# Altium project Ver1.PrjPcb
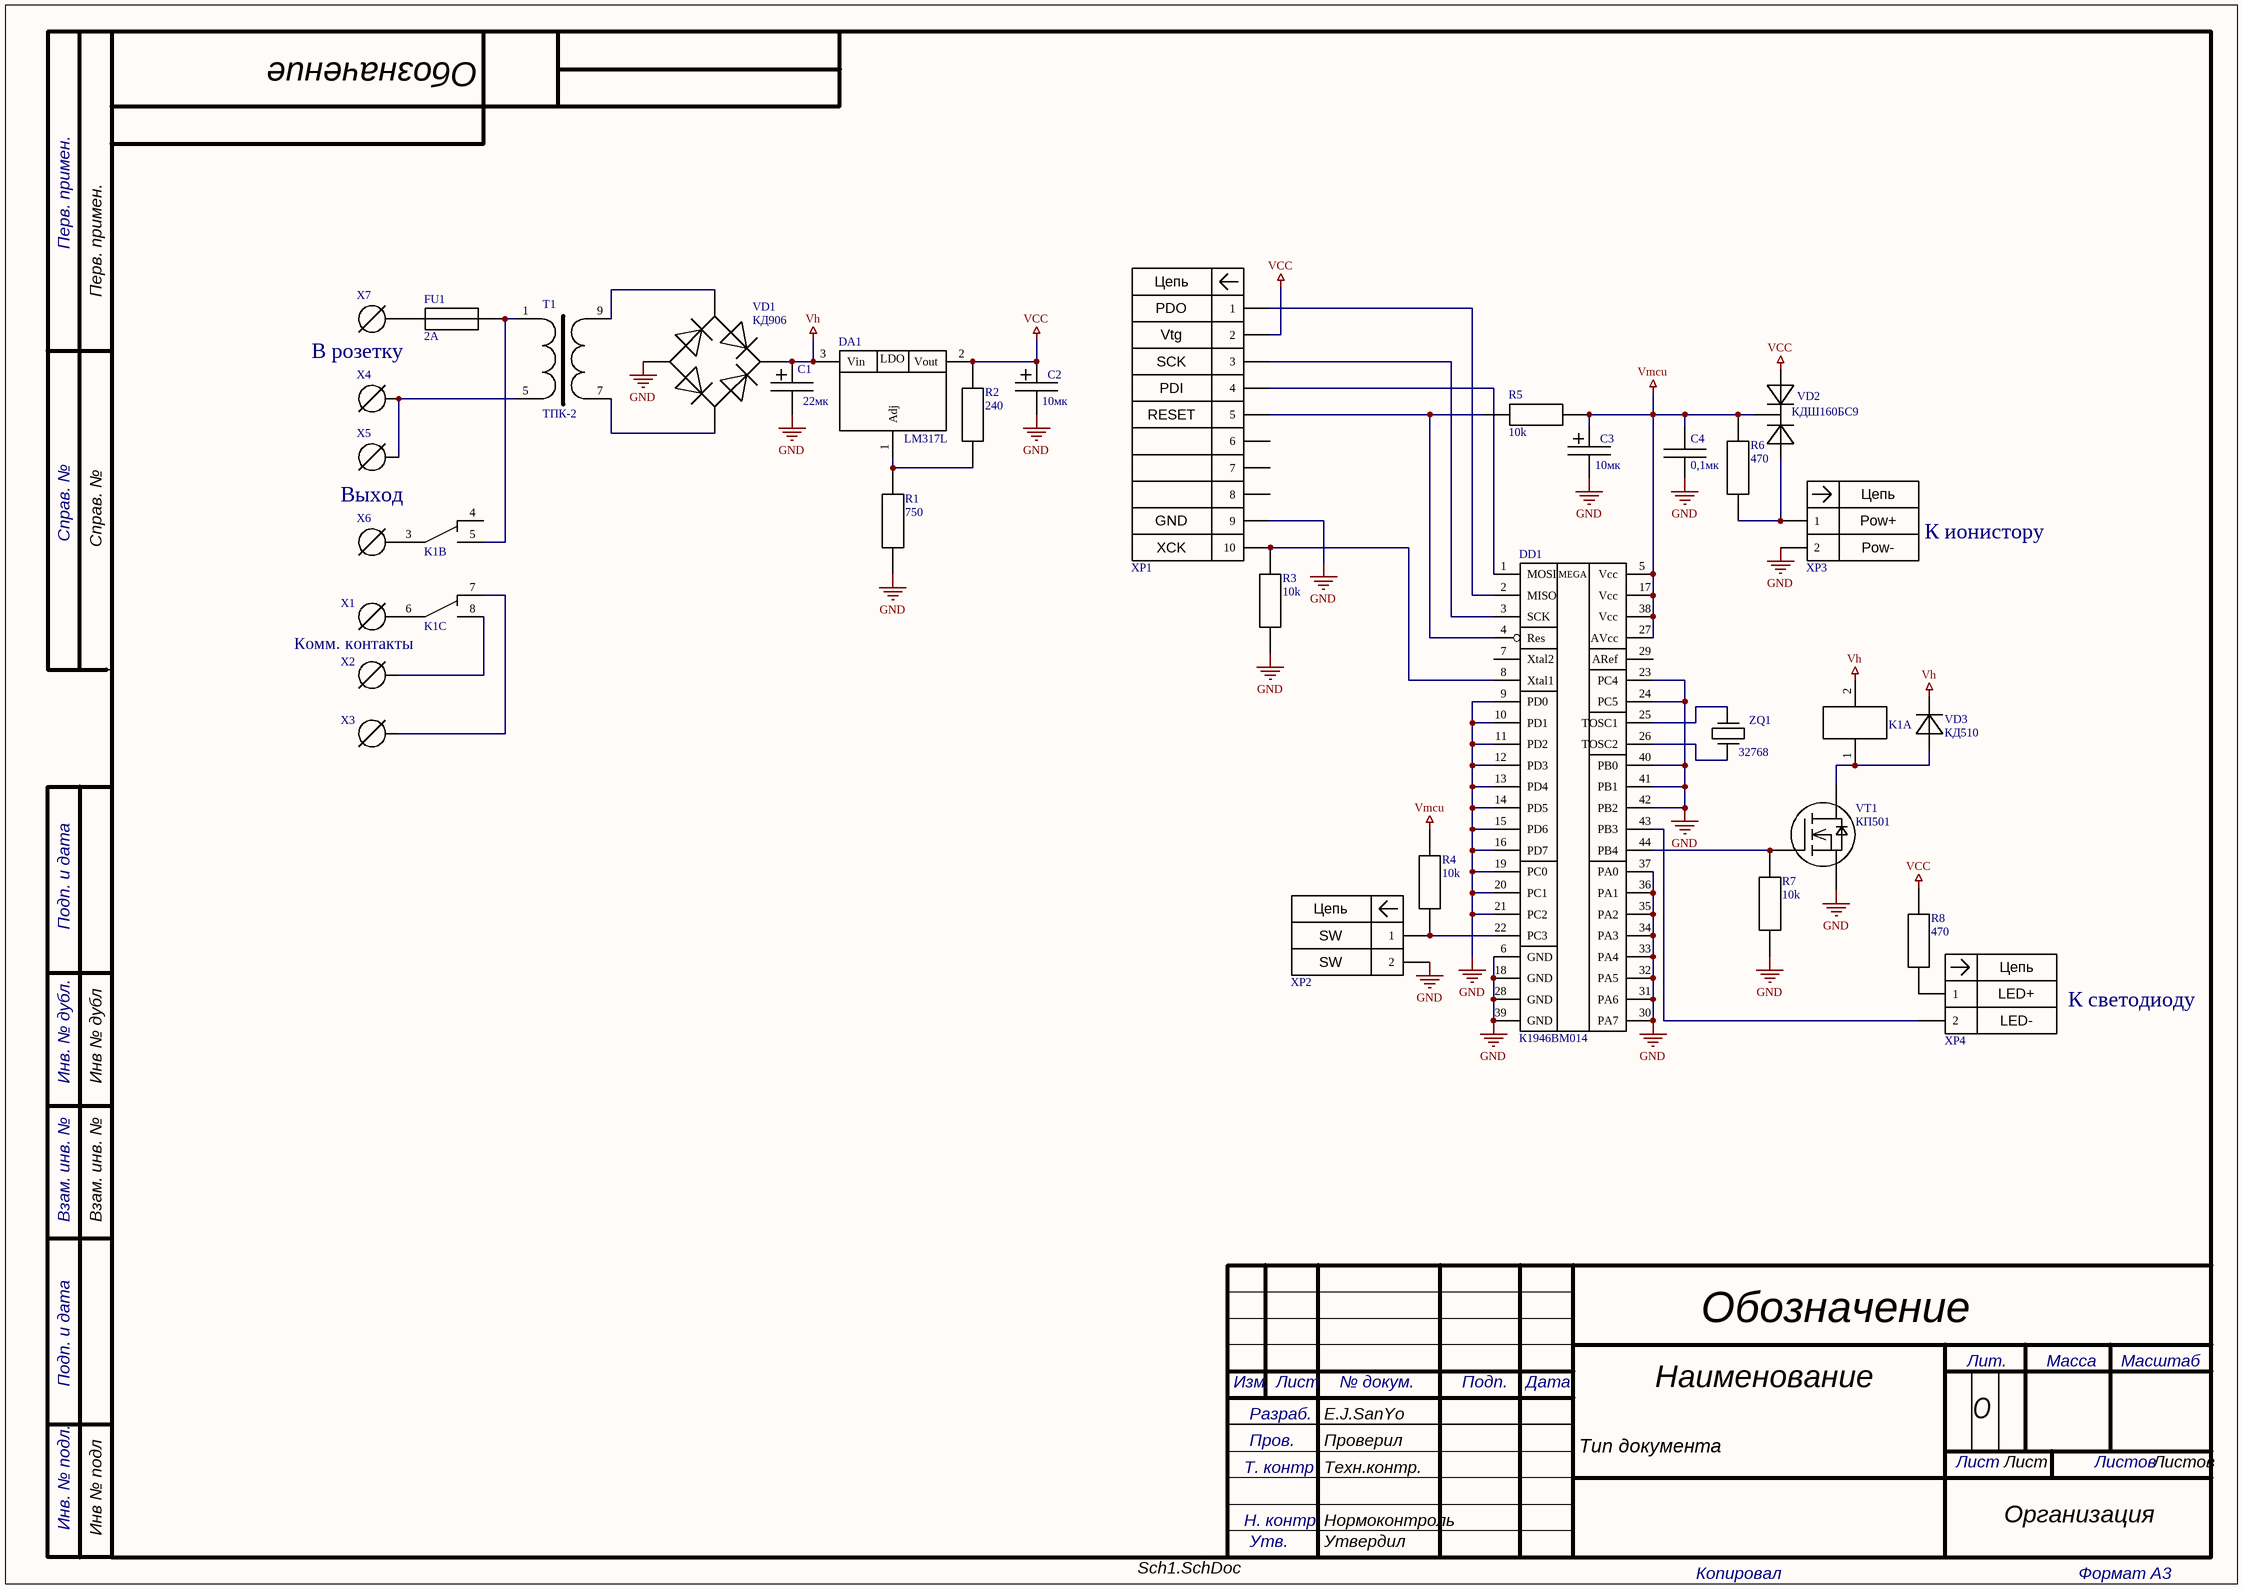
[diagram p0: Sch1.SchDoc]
1 sheet, 33 parts. Net scope: global (net labels, ports and power ports of the same name join across sheets).
Board file: PCB1.PcbDoc

## Sheet Sch1.SchDoc: Наименование
size 420 x 297 mm; ApprovedBy: Утвердил; CheckedBy: Проверил; Author: E.J.SanYo; CompanyName: Организация; DocumentNumber: Обозначение; SheetNumber: Лист; SheetTotal: Листов; TechContr: Техн.контр.; NormCotr: Нормоконтроль; DocumentType: Тип документа; InvNumOrigin: Инв № подл; InvNumDuplicate: Инв № дубл; InsteadOfInvNum: Взам. инв. №; RefNumber: Справ. №; InitialUsage: Перв. примен.; Lit: О

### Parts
C1  value 22мк  [Type E]  (hidden comment: Type E)
C2  value 10мк  [Type B]  (hidden comment: Type B)
C3  value 10мк  [Type B]  (hidden comment: Type B)
C4  value 0,1мк  [RC_1206]  (hidden comment: C_1206)
DA1  LM317L  [TO-92]
DD1  К1946ВМ014  [TQFP-44]
FU1  value 2A  [ВП2-1]  (hidden comment: Предохранитель)
K1  RP3  [RP3]  (value not drawn)  (parts A,B,C of 3)
R1  value 750  [RC_1206]  (hidden comment: R_1206)
R2  value 240  [RC_1206]  (hidden comment: R_1206)
R3  value 10k  [RC_1206]  (hidden comment: R_1206)
R4  value 10k  [RC_1206]  (hidden comment: R_1206)
R5  value 10k  [RC_1206]  (hidden comment: R_1206)
R6  value 470  [RC_1206]  (hidden comment: R_1206)
R7  value 10k  [RC_1206]  (hidden comment: R_1206)
R8  value 470  [RC_1206]  (hidden comment: R_1206)
T1  ТПК-2  [ТПГ-2]
VD1  КД906  [DB-1]
VD2  КДШ160БС9  [SOT-23]
VD3  КД510  [DO-35]
VT1  КП501  [TO-92]
X1  Клемма 1,7 мм  [Клемма 1,7 мм]  (value not drawn)
X2  Клемма 1,7 мм  [Клемма 1,7 мм]  (value not drawn)
X3  Клемма 1,7 мм  [Клемма 1,7 мм]  (value not drawn)
X4  Клемма 1,7 мм  [Клемма 1,7 мм]  (value not drawn)
X5  Клемма 1,7 мм  [Клемма 1,7 мм]  (value not drawn)
X6  Клемма 1,7 мм  [Клемма 1,7 мм]  (value not drawn)
X7  Клемма 1,7 мм  [Клемма 1,7 мм]  (value not drawn)
XP1  IDC_progr  [IDC-10MS]  (value not drawn)
XP2  Button  [PLS-2]  (value not drawn)
XP3  Pow  [PLS-2]  (value not drawn)
XP4  LED  [PLS-2]  (value not drawn)
ZQ1  value 32768  [DT-38T]  (hidden comment: DT-38T)

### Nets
GND: C1.2 C2.2 C3.2 C4.2 DD1.6(GND) DD1.9(PD0) DD1.10(PD1) DD1.11(PD2) DD1.12(PD3) DD1.13(PD4) DD1.14(PD5) DD1.15(PD6) DD1.16(PD7) DD1.18(GND) DD1.19(PC0) DD1.20(PC1) DD1.21(PC2) DD1.23(PC4) DD1.24(PC5) DD1.28(GND) DD1.30(PA7) DD1.31(PA6) DD1.32(PA5) DD1.33(PA4) DD1.34(PA3) DD1.35(PA2) DD1.36(PA1) DD1.37(PA0) DD1.39(GND) DD1.40(PB0) DD1.41(PB1) DD1.42(PB2) R1.2 R3.2 R7.2 VD1.4(-) VT1.3(sourse) XP1.9 XP2.2 XP3.2
VCC: C2.1 DA1.2(Vout) R2.1 R8.1 VD2.1 XP1.2
Vh: C1.1 DA1.3(Vin) K1.2 VD1.3(+) VD3.2
Vmcu: C3.1 C4.1 DD1.5(Vcc) DD1.17(Vcc) DD1.27(AVcc) DD1.38(Vcc) R4.1 R5.1 R6.1 VD2.3
NetDA1_1: DA1.1(Adj) R1.1 R2.2
NetDD1_1: DD1.1(MOSI) XP1.4
NetDD1_2: DD1.2(MISO) XP1.1
NetDD1_3: DD1.3(SCK) XP1.3
NetDD1_4: DD1.4(Res) R5.2 XP1.5
NetDD1_8: DD1.8(Xtal1) R3.1 XP1.10
NetDD1_22: DD1.22(PC3) R4.2 XP2.1
NetDD1_25: DD1.25(TOSC1) ZQ1.2
NetDD1_26: DD1.26(TOSC2) ZQ1.1
NetDD1_43: DD1.43(PB3) XP4.2
NetDD1_44: DD1.44(PB4) R7.1 VT1.1(gate)
NetFU1_1: FU1.1 X7.1
NetFU1_2: FU1.2 K1.5 T1.1
NetK1_1: K1.1 VD3.1 VT1.2(drain)
NetK1_3: K1.3 X6.1
NetK1_6: K1.6 X1.1
NetK1_7: K1.7 X3.1
NetK1_8: K1.8 X2.1
NetR6_2: R6.2 VD2.2 XP3.1
NetR8_2: R8.2 XP4.1
NetT1_5: T1.5 X4.1 X5.1
NetT1_7: T1.7 VD1.2(AC)
NetT1_9: T1.9 VD1.1(AC)

Not connected (* = marked no-connect by the designer): DD1 7(Xtal2) 29(ARef); K1 4; XP1 6 7 8

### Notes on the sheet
- В розетку
- Выход
- К ионистору
- Комм. контакты
- К светодиоду

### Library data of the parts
VD1 = DB102
VD3 = 1N4148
